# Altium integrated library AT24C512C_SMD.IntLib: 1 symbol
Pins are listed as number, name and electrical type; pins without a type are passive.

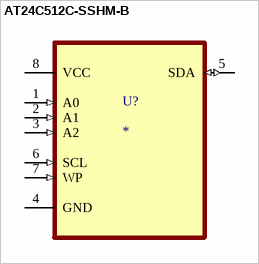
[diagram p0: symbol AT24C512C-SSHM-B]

## AT24C512C-SSHM-B
designator U?
EEPROM Memory IC 512Kb (64K x 8) IÂ²C 400 kHz 900 ns 8-SOIC; MF: Microchip; MP: AT24C512C-SSHM-B
footprint SOIC127P600X175-8N
pins: 1 A0 (in), 2 A1 (in), 3 A2 (in), 4 GND, 5 SDA (io), 6 SCL (in), 7 WP (in), 8 VCC (power)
